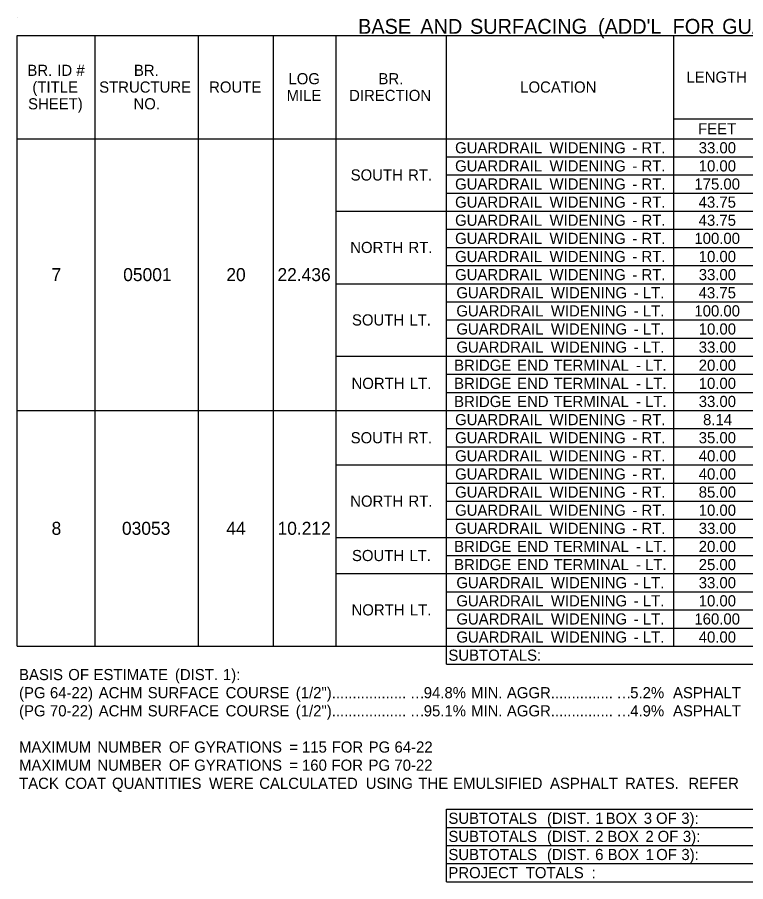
# Model space of a CAD drawing. Extents: x 542596 to 1930787, y -1948294 to 596640.
# Drawn here: x 554098.7 to 554490.8, y -1946673.7 to -1946208.7 of the extents above; entities that cross this region are included whole.
import ezdxf

# ---------------------------------------------------------------- set-up
doc = ezdxf.new("R2010")
doc.units = 0
doc.layers.add('Default', color=7, linetype='Continuous')

msp = doc.modelspace()

# ---------------------------------------------------------------- linework, layer by layer
at = {"layer": 'Default'}
for p, q in [((554098.71, -1946208.65), (554098.71, -1946208.65)), ((554098.71, -1946218.4), (554847.51, -1946218.4)), ((554098.71, -1946546.98), (554098.71, -1946218.4)), ((554140.63, -1946273.98), (554140.63, -1946218.4)), ((554196.21, -1946273.98), (554196.21, -1946218.4)), ((554236.67, -1946273.98), (554236.67, -1946218.4)), ((554270.31, -1946546.98), (554270.31, -1946218.4)), ((554329.78, -1946556.73), (554329.78, -1946218.4)), ((554452.15, -1946546.98), (554452.15, -1946218.4)), ((554452.15, -1946263.25), (554499.43, -1946263.25)), ((554098.71, -1946273.98), (554847.51, -1946273.98)), ((554140.63, -1946546.98), (554140.63, -1946273.98)), ((554196.21, -1946546.98), (554196.21, -1946273.98)), ((554236.67, -1946546.98), (554236.67, -1946273.98)), ((554452.15, -1946342.23), (554452.15, -1946273.98)), ((554329.78, -1946283.73), (554847.51, -1946283.73)), ((554329.78, -1946293.48), (554847.51, -1946293.48)), ((554329.78, -1946303.23), (554847.51, -1946303.23)), ((554270.31, -1946312.98), (554329.78, -1946312.98)), ((554329.78, -1946312.98), (554797.78, -1946312.98)), ((554329.78, -1946322.73), (554847.51, -1946322.73)), ((554329.78, -1946332.48), (554847.51, -1946332.48)), ((554329.78, -1946342.23), (554847.51, -1946342.23)), ((554270.31, -1946351.98), (554329.78, -1946351.98)), ((554329.78, -1946351.98), (554847.51, -1946351.98)), ((554452.15, -1946390.98), (554452.15, -1946351.98)), ((554329.78, -1946361.73), (554847.51, -1946361.73)), ((554329.78, -1946371.48), (554847.51, -1946371.48)), ((554329.78, -1946381.23), (554847.51, -1946381.23)), ((554270.31, -1946390.98), (554329.78, -1946390.98)), ((554329.78, -1946390.98), (554847.51, -1946390.98)), ((554329.78, -1946400.73), (554847.51, -1946400.73)), ((554329.78, -1946410.48), (554847.51, -1946410.48)), ((554098.71, -1946420.23), (554329.78, -1946420.23)), ((554098.71, -1946420.23), (554329.78, -1946420.23)), ((554329.78, -1946420.23), (554847.51, -1946420.23)), ((554452.15, -1946488.48), (554452.15, -1946420.23)), ((554329.78, -1946429.98), (554847.51, -1946429.98)), ((554329.78, -1946439.73), (554847.51, -1946439.73)), ((554270.31, -1946449.48), (554329.78, -1946449.48)), ((554329.78, -1946449.48), (554847.51, -1946449.48)), ((554329.78, -1946459.23), (554847.51, -1946459.23)), ((554329.78, -1946468.98), (554847.51, -1946468.98)), ((554329.78, -1946478.73), (554847.51, -1946478.73)), ((554270.31, -1946488.48), (554847.51, -1946488.48)), ((554270.31, -1946488.48), (554329.78, -1946488.48)), ((554329.78, -1946498.23), (554847.51, -1946498.23)), ((554270.31, -1946507.98), (554329.78, -1946507.98)), ((554329.78, -1946507.98), (554847.51, -1946507.98)), ((554452.15, -1946546.98), (554452.15, -1946507.98)), ((554329.78, -1946517.73), (554847.51, -1946517.73)), ((554329.78, -1946527.48), (554847.51, -1946527.48)), ((554329.78, -1946537.23), (554847.51, -1946537.23)), ((554098.71, -1946546.98), (554847.51, -1946546.98)), ((554329.78, -1946556.73), (554329.78, -1946546.98)), ((554329.78, -1946556.73), (554847.51, -1946556.73)), ((554329.78, -1946634.73), (554847.51, -1946634.73)), ((554329.78, -1946634.73), (554847.51, -1946634.73)), ((554329.78, -1946673.73), (554329.78, -1946634.73)), ((554329.78, -1946673.73), (554329.78, -1946634.73)), ((554329.78, -1946644.48), (554847.51, -1946644.48)), ((554329.78, -1946654.23), (554847.51, -1946654.23)), ((554329.78, -1946663.98), (554847.51, -1946663.98)), ((554329.78, -1946673.73), (554847.51, -1946673.73))]:
    msp.add_line(p, q, dxfattribs=at)

# ---------------------------------------------------------------- texts
for s, height, p in [('BASE', 8, (554282.16, -1946217.53)), (' AND', 8, (554312.67, -1946217.53)), (' SURFACING', 8, (554339.43, -1946217.53)), (" (ADD'L", 8, (554408.31, -1946217.53)), (' FOR', 8, (554448.51, -1946217.53)), (' GUARDRAIL)', 8, (554475.15, -1946217.53)), ('BR.', 6, (554104.15, -1946240.19)), (' ID', 6, (554118.01, -1946240.19)), (' #', 6, (554128.3, -1946240.19)), ('BR.', 6, (554161.49, -1946240.19)), ('LOG', 6, (554244.66, -1946244.69)), ('BR.', 6, (554293.12, -1946244.69)), ('LENGTH', 6, (554458.88, -1946243.83)), ('(TITLE', 6, (554106.84, -1946249.19)), ('STRUCTURE', 6, (554142.78, -1946249.19)), ('ROUTE', 6, (554201.98, -1946249.19)), ('LOCATION', 6, (554369.41, -1946249.19)), ('MILE', 6, (554243.69, -1946253.69)), ('DIRECTION', 6, (554277.33, -1946253.69)), ('SHEET)', 6, (554104.52, -1946258.19)), ('NO.', 6, (554161.26, -1946258.19)), ('FEET', 6, (554465.16, -1946271.62)), ('GUARDRAIL', 6, (554334.35, -1946281.85)), (' WIDENING', 6, (554382.97, -1946281.85)), (' RT.', 6, (554432.48, -1946281.85)), ('33.00', 6, (554465.51, -1946281.85)), (' -', 6, (554427.62, -1946281.85)), ('GUARDRAIL', 6, (554334.35, -1946291.6)), (' WIDENING', 6, (554382.97, -1946291.6)), (' RT.', 6, (554432.48, -1946291.6)), ('10.00', 6, (554465.51, -1946291.6)), ('SOUTH', 6, (554278.16, -1946296.48)), (' RT.', 6, (554306.83, -1946296.48)), (' -', 6, (554427.62, -1946291.6)), ('GUARDRAIL', 6, (554334.35, -1946301.35)), (' WIDENING', 6, (554382.97, -1946301.35)), (' RT.', 6, (554432.48, -1946301.35)), ('175.00', 6, (554463.18, -1946301.35)), (' -', 6, (554427.62, -1946301.35)), ('GUARDRAIL', 6, (554334.35, -1946311.1)), (' WIDENING', 6, (554382.97, -1946311.1)), (' RT.', 6, (554432.48, -1946311.1)), ('43.75', 6, (554465.47, -1946311.1)), (' -', 6, (554427.62, -1946311.1)), ('GUARDRAIL', 6, (554334.35, -1946320.85)), (' WIDENING', 6, (554382.97, -1946320.85)), (' RT.', 6, (554432.48, -1946320.85)), ('43.75', 6, (554465.47, -1946320.85)), (' -', 6, (554427.62, -1946320.85)), ('GUARDRAIL', 6, (554334.35, -1946330.6)), (' WIDENING', 6, (554382.97, -1946330.6)), (' RT.', 6, (554432.48, -1946330.6)), ('100.00', 6, (554463.18, -1946330.6)), ('NORTH', 6, (554277.93, -1946335.48)), (' RT.', 6, (554307.06, -1946335.48)), (' -', 6, (554427.62, -1946330.6)), ('GUARDRAIL', 6, (554334.35, -1946340.35)), (' WIDENING', 6, (554382.97, -1946340.35)), (' -', 6, (554427.62, -1946340.35)), (' RT.', 6, (554432.48, -1946340.35)), ('10.00', 6, (554465.51, -1946340.35)), ('05001', 7, (554155.73, -1946350.6)), ('20', 7, (554211.24, -1946350.6)), ('22.436', 7, (554238.76, -1946350.6)), ('7', 7, (554117.17, -1946350.6)), ('GUARDRAIL', 6, (554334.35, -1946350.1)), (' WIDENING', 6, (554382.97, -1946350.1)), (' -', 6, (554427.62, -1946350.1)), (' RT.', 6, (554432.48, -1946350.1)), ('33.00', 6, (554465.51, -1946350.1)), ('GUARDRAIL', 6, (554335.05, -1946359.85)), (' WIDENING', 6, (554383.67, -1946359.85)), (' -', 6, (554428.32, -1946359.85)), (' LT.', 6, (554433.17, -1946359.85)), ('43.75', 6, (554465.47, -1946359.85)), ('GUARDRAIL', 6, (554335.05, -1946369.6)), (' WIDENING', 6, (554383.67, -1946369.6)), (' LT.', 6, (554433.17, -1946369.6)), ('100.00', 6, (554463.18, -1946369.6)), ('SOUTH', 6, (554278.86, -1946374.48)), (' LT.', 6, (554307.53, -1946374.48)), (' -', 6, (554428.32, -1946369.6)), ('GUARDRAIL', 6, (554335.05, -1946379.35)), (' WIDENING', 6, (554383.67, -1946379.35)), (' LT.', 6, (554433.17, -1946379.35)), ('10.00', 6, (554465.51, -1946379.35)), (' -', 6, (554428.32, -1946379.35)), ('GUARDRAIL', 6, (554335.05, -1946389.1)), (' WIDENING', 6, (554383.67, -1946389.1)), (' LT.', 6, (554433.17, -1946389.1)), ('33.00', 6, (554465.51, -1946389.1)), (' -', 6, (554428.32, -1946389.1)), ('BRIDGE', 6, (554333.83, -1946398.85)), (' END', 6, (554365.53, -1946398.85)), (' TERMINAL', 6, (554385.11, -1946398.85)), (' LT.', 6, (554434.39, -1946398.85)), ('20.00', 6, (554465.51, -1946398.85)), (' -', 6, (554429.53, -1946398.85)), ('NORTH', 6, (554278.63, -1946408.6)), (' LT.', 6, (554307.76, -1946408.6)), ('BRIDGE', 6, (554333.83, -1946408.6)), (' END', 6, (554365.53, -1946408.6)), (' TERMINAL', 6, (554385.11, -1946408.6)), (' LT.', 6, (554434.39, -1946408.6)), ('10.00', 6, (554465.51, -1946408.6)), (' -', 6, (554429.53, -1946408.6)), ('BRIDGE', 6, (554333.83, -1946418.35)), (' END', 6, (554365.53, -1946418.35)), (' TERMINAL', 6, (554385.11, -1946418.35)), (' LT.', 6, (554434.39, -1946418.35)), ('33.00', 6, (554465.51, -1946418.35)), (' -', 6, (554429.53, -1946418.35)), ('GUARDRAIL', 6, (554334.35, -1946428.1)), (' WIDENING', 6, (554382.97, -1946428.1)), (' RT.', 6, (554432.48, -1946428.1)), ('8.14', 6, (554467.84, -1946428.1)), (' -', 6, (554427.62, -1946428.1)), ('SOUTH', 6, (554278.16, -1946437.85)), (' RT.', 6, (554306.83, -1946437.85)), ('GUARDRAIL', 6, (554334.35, -1946437.85)), (' WIDENING', 6, (554382.97, -1946437.85)), (' RT.', 6, (554432.48, -1946437.85)), ('35.00', 6, (554465.51, -1946437.85)), (' -', 6, (554427.62, -1946437.85)), ('GUARDRAIL', 6, (554334.35, -1946447.6)), (' WIDENING', 6, (554382.97, -1946447.6)), (' -', 6, (554427.62, -1946447.6)), (' RT.', 6, (554432.48, -1946447.6)), ('40.00', 6, (554465.51, -1946447.6)), ('GUARDRAIL', 6, (554334.35, -1946457.35)), (' WIDENING', 6, (554382.97, -1946457.35)), (' -', 6, (554427.62, -1946457.35)), (' RT.', 6, (554432.48, -1946457.35)), ('40.00', 6, (554465.51, -1946457.35)), ('GUARDRAIL', 6, (554334.35, -1946467.1)), (' WIDENING', 6, (554382.97, -1946467.1)), (' RT.', 6, (554432.48, -1946467.1)), ('85.00', 6, (554465.51, -1946467.1)), ('NORTH', 6, (554277.93, -1946471.98)), (' RT.', 6, (554307.06, -1946471.98)), (' -', 6, (554427.62, -1946467.1)), ('GUARDRAIL', 6, (554334.35, -1946476.85)), (' WIDENING', 6, (554382.97, -1946476.85)), (' RT.', 6, (554432.48, -1946476.85)), ('10.00', 6, (554465.51, -1946476.85)), (' -', 6, (554427.62, -1946476.85)), ('8', 7, (554117.17, -1946487.1)), ('03053', 7, (554155.05, -1946487.1)), ('44', 7, (554211.24, -1946487.1)), ('10.212', 7, (554238.8, -1946487.1)), ('GUARDRAIL', 6, (554334.35, -1946486.6)), (' WIDENING', 6, (554382.97, -1946486.6)), (' RT.', 6, (554432.48, -1946486.6)), ('33.00', 6, (554465.51, -1946486.6)), (' -', 6, (554427.62, -1946486.6)), ('BRIDGE', 6, (554333.83, -1946496.35)), (' END', 6, (554365.53, -1946496.35)), (' TERMINAL', 6, (554385.11, -1946496.35)), (' LT.', 6, (554434.39, -1946496.35)), ('20.00', 6, (554465.51, -1946496.35)), ('SOUTH', 6, (554278.86, -1946501.23)), (' LT.', 6, (554307.53, -1946501.23)), (' -', 6, (554429.53, -1946496.35)), ('BRIDGE', 6, (554333.83, -1946506.1)), (' END', 6, (554365.53, -1946506.1)), (' TERMINAL', 6, (554385.11, -1946506.1)), (' LT.', 6, (554434.39, -1946506.1)), ('25.00', 6, (554465.51, -1946506.1)), (' -', 6, (554429.53, -1946506.1)), ('GUARDRAIL', 6, (554335.05, -1946515.85)), (' WIDENING', 6, (554383.67, -1946515.85)), (' LT.', 6, (554433.17, -1946515.85)), ('33.00', 6, (554465.51, -1946515.85)), (' -', 6, (554428.32, -1946515.85)), ('GUARDRAIL', 6, (554335.05, -1946525.6)), (' WIDENING', 6, (554383.67, -1946525.6)), (' LT.', 6, (554433.17, -1946525.6)), ('10.00', 6, (554465.51, -1946525.6)), ('NORTH', 6, (554278.63, -1946530.48)), (' LT.', 6, (554307.76, -1946530.48)), (' -', 6, (554428.32, -1946525.6)), ('GUARDRAIL', 6, (554335.05, -1946535.35)), (' WIDENING', 6, (554383.67, -1946535.35)), (' LT.', 6, (554433.17, -1946535.35)), ('160.00', 6, (554463.18, -1946535.35)), (' -', 6, (554428.32, -1946535.35)), ('GUARDRAIL', 6, (554335.05, -1946545.1)), (' WIDENING', 6, (554383.67, -1946545.1)), (' -', 6, (554428.32, -1946545.1)), (' LT.', 6, (554433.17, -1946545.1)), ('40.00', 6, (554465.51, -1946545.1)), ('SUBTOTALS:', 6, (554330.76, -1946554.85)), ('BASIS', 6, (554099.68, -1946565.28)), (' OF', 6, (554123.94, -1946565.28)), (' ESTIMATE', 6, (554137.53, -1946565.28)), (' (DIST.', 6, (554181.34, -1946565.28)), (' 1):', 6, (554207.15, -1946565.28)), ('(PG', 6, (554099.68, -1946575.03)), (' 64-22)', 6, (554114.06, -1946575.03)), (' ACHM', 6, (554140.31, -1946575.03)), (' SURFACE', 6, (554166.69, -1946575.03)), (' COURSE', 6, (554208.63, -1946575.03)), (' (1/2")..................', 6, (554246.39, -1946575.03)), ('94.8%', 6, (554317.49, -1946575.03)), (' MIN.', 6, (554340.73, -1946575.03)), (' AGGR...............', 6, (554360.02, -1946575.03)), ('5.2%', 6, (554428.62, -1946575.03)), ('  ASPHALT', 6, (554447.2, -1946575.03)), ('…', 6, (554310.09, -1946575.03)), ('…', 6, (554421.22, -1946575.03)), ('(PG', 6, (554099.68, -1946584.78)), (' 70-22)', 6, (554114.06, -1946584.78)), (' ACHM', 6, (554140.31, -1946584.78)), (' SURFACE', 6, (554166.69, -1946584.78)), (' COURSE', 6, (554208.63, -1946584.78)), (' (1/2")..................', 6, (554246.39, -1946584.78)), ('95.1%', 6, (554317.49, -1946584.78)), (' MIN.', 6, (554340.73, -1946584.78)), (' AGGR...............', 6, (554360.02, -1946584.78)), ('4.9%', 6, (554428.62, -1946584.78)), ('  ASPHALT', 6, (554447.2, -1946584.78)), ('…', 6, (554310.09, -1946584.78)), ('…', 6, (554421.22, -1946584.78)), ('MAXIMUM', 6, (554099.68, -1946604.28)), (' NUMBER', 6, (554139.57, -1946604.28)), (' OF', 6, (554178.12, -1946604.28)), (' GYRATIONS', 6, (554191.71, -1946604.28)), (' 115', 6, (554249.73, -1946604.28)), (' FOR', 6, (554265.7, -1946604.28)), (' PG', 6, (554285.62, -1946604.28)), (' 64-22', 6, (554299.53, -1946604.28)), (' =', 6, (554242.97, -1946604.28)), ('MAXIMUM', 6, (554099.68, -1946614.03)), (' NUMBER', 6, (554139.57, -1946614.03)), (' OF', 6, (554178.12, -1946614.03)), (' GYRATIONS', 6, (554191.71, -1946614.03)), (' 160', 6, (554249.73, -1946614.03)), (' FOR', 6, (554265.63, -1946614.03)), (' PG', 6, (554285.55, -1946614.03)), (' 70-22', 6, (554299.46, -1946614.03)), (' =', 6, (554242.97, -1946614.03)), ('TACK', 6, (554099.68, -1946623.78)), (' COAT', 6, (554122.03, -1946623.78)), (' QUANTITIES', 6, (554147.48, -1946623.78)), (' WERE', 6, (554199.68, -1946623.78)), (' CALCULATED', 6, (554226.71, -1946623.78)), (' USING', 6, (554284.03, -1946623.78)), (' THE', 6, (554312.38, -1946623.78)), (' EMULSIFIED', 6, (554331.03, -1946623.78)), (' ASPHALT', 6, (554383.22, -1946623.78)), (' RATES.', 6, (554423.59, -1946623.78)), ('  REFER', 6, (554455.47, -1946623.78)), ('SUBTOTALS', 6, (554330.76, -1946642.6)), (' (DIST.', 6, (554381.58, -1946642.6)), (' BOX', 6, (554413.18, -1946642.6)), (' 3', 6, (554433.67, -1946642.6)), (' OF', 6, (554440.3, -1946642.6)), (' 3):', 6, (554453.88, -1946642.6)), (' 1', 6, (554407.55, -1946642.6)), ('SUBTOTALS', 6, (554330.76, -1946652.35)), (' (DIST.', 6, (554381.58, -1946652.35)), (' 2', 6, (554407.55, -1946652.35)), (' BOX', 6, (554414.12, -1946652.35)), (' 2', 6, (554434.61, -1946652.35)), (' OF', 6, (554441.17, -1946652.35)), (' 3):', 6, (554454.76, -1946652.35)), ('SUBTOTALS', 6, (554330.76, -1946662.1)), (' (DIST.', 6, (554381.58, -1946662.1)), (' 6', 6, (554407.55, -1946662.1)), (' BOX', 6, (554414.24, -1946662.1)), (' 1', 6, (554434.73, -1946662.1)), (' OF', 6, (554440.36, -1946662.1)), (' 3):', 6, (554453.94, -1946662.1)), ('PROJECT', 6, (554330.76, -1946671.85)), (' TOTALS', 6, (554370.18, -1946671.85)), (' :', 6, (554405.64, -1946671.85))]:
    msp.add_text(s, height=height, dxfattribs=at).set_placement(p)

doc.saveas('drawing.dxf')
